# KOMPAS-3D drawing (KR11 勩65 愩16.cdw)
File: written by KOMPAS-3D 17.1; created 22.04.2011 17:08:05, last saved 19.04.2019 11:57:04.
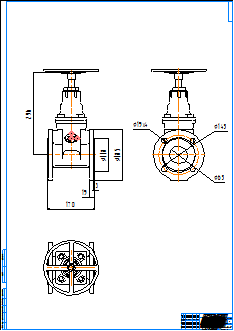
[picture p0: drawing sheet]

Title block, sheet 1: name: KR11 Ду65 Ру16; material: Внимание! Данный продукт является объектом авторского права ООО «Торговый Дом АДЛ». / Запрещается изменение, копирование, распространение / (в том числе путем копирования на другие сайты и ресурсы в Интернете) / или любое иное использование информации и объектов без предварительного / согласия правообладателя (ООО «Торговый Дом АДЛ»).; scale: 1:1; sheets: 1; organisation: ООО "Торговый дом АДЛ"; sheet format: A0; stored path: \\adlc.lan\data\АДЛ_ПКД\3D-модели\ADL production\Клиновые задвижки серии KR ГРАНАР\Клиновые задвижки KR11\KOMPAS 2D\KR11 Ду65 Ру16.cdw

Views: Спереди 4
Dimensions and other numbers on the sheet: 170; 19; 3; 185; 118; 296; 1:1; 1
